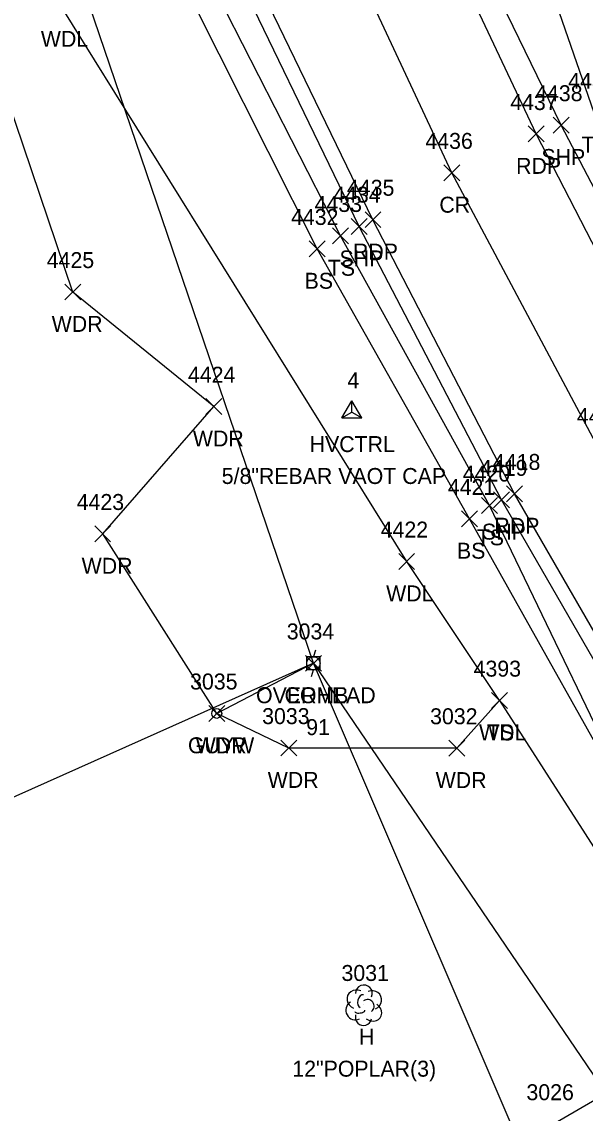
# Model space of a CAD drawing. Extents: x 1601151 to 1602912, y 499508 to 501770.
# Drawn here: x 1601741 to 1601811.7, y 499859.1 to 499996 of the extents above; entities that cross this region are included whole.
import ezdxf

# ---------------------------------------------------------------- set-up
doc = ezdxf.new("R2010")
doc.units = 0
for name, color, linetype in [('C_A', 7, 'Continuous'), ('C_C', 7, 'Continuous'), ('C_I', 7, 'Continuous'), ('CPSM', 7, 'Continuous'), ('L_A', 7, 'Continuous'), ('L_C', 7, 'Continuous'), ('L_I', 7, 'Continuous'), ('L_TIC', 7, 'Continuous'), ('LAWA', 7, 'Continuous'), ('LELB', 7, 'Continuous'), ('LTD', 7, 'Continuous'), ('P_A', 7, 'Continuous'), ('P_I', 7, 'Continuous'), ('P_TIC', 7, 'Continuous'), ('PET', 7, 'Continuous'), ('PRC', 7, 'Continuous'), ('PSP', 7, 'Continuous'), ('R_I', 7, 'Continuous'), ('RDG', 7, 'Continuous'), ('U_A', 7, 'Continuous'), ('U_C', 7, 'Continuous'), ('U_I', 7, 'Continuous'), ('U_TIC', 7, 'Continuous'), ('UCO', 7, 'Continuous'), ('UP', 7, 'Continuous'), ('UPGW', 7, 'Continuous')]:
    doc.layers.add(name, color=color, linetype=linetype)

msp = doc.modelspace()

# ---------------------------------------------------------------- linework, layer by layer
at = {"layer": 'CPSM'}
for p, q in [((1601781.19, 499946.29), (1601782.44, 499948.45)), ((1601783.69, 499946.29), (1601782.44, 499948.45)), ((1601782.44, 499947.01), (1601782.44, 499948.45)), ((1601781.19, 499946.29), (1601782.44, 499947.01)), ((1601781.19, 499946.29), (1601783.69, 499946.29)), ((1601782.44, 499947.01), (1601782.44, 499947.01)), ((1601782.44, 499947.01), (1601783.69, 499946.29))]:
    msp.add_line(p, q, dxfattribs=at)
at = {"layer": 'L_TIC'}
for points in [[(1601780.01, 499968.12), (1601782.01, 499970.12)], [(1601782.01, 499968.12), (1601780.01, 499970.12)], [(1601777.06, 499966.49), (1601779.06, 499968.49)], [(1601779.06, 499966.49), (1601777.06, 499968.49)], [(1601746.4, 499961.08), (1601748.4, 499963.08)], [(1601748.4, 499961.08), (1601746.4, 499963.08)], [(1601764.12, 499946.71), (1601766.12, 499948.71)], [(1601766.12, 499946.71), (1601764.12, 499948.71)], [(1601798.69, 499934.32), (1601800.69, 499936.32)], [(1601800.69, 499934.32), (1601798.69, 499936.32)], [(1601796.18, 499932.64), (1601798.18, 499934.64)], [(1601798.18, 499932.64), (1601796.18, 499934.64)], [(1601750.16, 499930.75), (1601752.16, 499932.75)], [(1601752.16, 499930.75), (1601750.16, 499932.75)], [(1601788.31, 499927.29), (1601790.31, 499929.29)], [(1601790.31, 499927.29), (1601788.31, 499929.29)], [(1601799.97, 499909.85), (1601801.97, 499911.85)], [(1601801.97, 499909.85), (1601799.97, 499911.85)], [(1601799.97, 499909.85), (1601801.97, 499911.85)], [(1601801.97, 499909.85), (1601799.97, 499911.85)], [(1601764.47, 499908.24), (1601766.47, 499910.24)], [(1601766.47, 499908.24), (1601764.47, 499910.24)], [(1601773.51, 499903.9), (1601775.51, 499905.9)], [(1601775.51, 499903.9), (1601773.51, 499905.9)], [(1601794.59, 499903.88), (1601796.59, 499905.88)], [(1601796.59, 499903.88), (1601794.59, 499905.88)]]:
    msp.add_lwpolyline(points, dxfattribs=at)
at = {"layer": 'LAWA'}
for points in [[(1601800.97, 499910.85), (1601789.31, 499928.29), (1601745.98, 499997.83), (1601720.73, 500050.45), (1601707.02, 500079.12), (1601696.06, 500108.93)], [(1601795.59, 499904.88), (1601774.51, 499904.9), (1601765.47, 499909.24), (1601751.16, 499931.75), (1601765.12, 499947.71), (1601747.4, 499962.08), (1601734.99, 499998.67), (1601711.23, 500024.72)], [(1601800.97, 499910.85), (1601795.59, 499904.88)]]:
    msp.add_lwpolyline(points, dxfattribs=at)
at = {"layer": 'LELB'}
for points in [[(1601817.31, 499872.7), (1601822.26, 499874.94), (1601824.19, 499882.19), (1601820.64, 499891.83), (1601797.18, 499933.64), (1601778.06, 499967.49), (1601759.63, 500004.16), (1601735.92, 500054.97), (1601725.84, 500087), (1601715.25, 500119.3), (1601698.06, 500177.62), (1601684.73, 500227.08), (1601672.09, 500269.9), (1601659.22, 500313.1), (1601655.82, 500330.46)], [(1601820.64, 499891.83), (1601799.69, 499935.32), (1601781.01, 499969.12), (1601762.54, 500005.3), (1601740.72, 500057.2), (1601729.05, 500088.56), (1601717.64, 500121.66), (1601699.62, 500177.82), (1601686.02, 500227.23), (1601673.93, 500270.73), (1601661.95, 500313.91), (1601655.82, 500330.46)], [(1601931.2, 499782.14), (1601903.71, 499827.94), (1601870.02, 499876.47), (1601851.57, 499910.98), (1601830.01, 499949.1), (1601812.84, 499984.56), (1601799.79, 500022.21), (1601775.51, 500071.18), (1601768.77, 500104.65), (1601752.69, 500132.35), (1601745.59, 500147.03), (1601736.89, 500188.62), (1601718.63, 500236.24), (1601706.47, 500280.22)], [(1601800.97, 499910.85), (1601817.26, 499885.48), (1601817.31, 499872.7)]]:
    msp.add_lwpolyline(points, dxfattribs=at)
at = {"layer": 'LTD'}
msp.add_line((1601783.9, 499872.69), (1601783.9, 499872.69), dxfattribs=at)
msp.add_line((1601783.9, 499872.69), (1601783.9, 499872.69), dxfattribs=at)
msp.add_arc((1601783.95, 499874.13), 1.05, 335.5272, 180.9563, dxfattribs=at)
for centre, major_axis, ratio, start_param, end_param in [((1601783.11, 499873.36), (1.21, -0.51), 0.895232, 1.570796, 4.712389), ((1601784.94, 499873.28), (-1.14, -0.48), 0.949671, 1.570796, 4.712389), ((1601783.69, 499873.15), (-0.208, -0.792), 0.645439, 3.141593, 6.283185), ((1601784.4, 499872.53), (-0.5, 0.667), 0.989748, 3.141593, 6.283185), ((1601782.82, 499871.99), (0.58, -1.04), 0.959034, 3.141593, 6.283185), ((1601783.44, 499871.94), (-0.625, -0.083), 0.423636, 0, 3.141593), ((1601784.9, 499871.86), (-1.09, 0.79), 0.841452, 1.570796, 4.712389), ((1601783.9, 499871.19), (0.26, 1.06), 0.942809, 1.570796, 4.712389)]:
    msp.add_ellipse(centre, major_axis=major_axis, ratio=ratio, start_param=start_param, end_param=end_param, dxfattribs=at)
at = {"layer": 'P_TIC'}
for points in [[(1601804.55, 499980.9), (1601806.55, 499982.9)], [(1601806.55, 499980.9), (1601804.55, 499982.9)], [(1601807.69, 499982.01), (1601809.69, 499984.01)], [(1601809.69, 499982.01), (1601807.69, 499984.01)], [(1601793.98, 499976.03), (1601795.98, 499978.03)], [(1601795.98, 499976.03), (1601793.98, 499978.03)], [(1601784.08, 499970.15), (1601786.08, 499972.15)], [(1601786.08, 499970.15), (1601784.08, 499972.15)], [(1601782.34, 499969.29), (1601784.34, 499971.29)], [(1601784.34, 499969.29), (1601782.34, 499971.29)], [(1601801.83, 499935.77), (1601803.83, 499937.77)], [(1601803.83, 499935.77), (1601801.83, 499937.77)], [(1601800.22, 499935.03), (1601802.22, 499937.03)], [(1601802.22, 499935.03), (1601800.22, 499937.03)]]:
    msp.add_lwpolyline(points, dxfattribs=at)
at = {"layer": 'PET'}
for points in [[(1601995.67, 499683.24), (1601967.44, 499723.89), (1601951.2, 499747.81), (1601928.38, 499780.82), (1601898.7, 499825.12), (1601866.23, 499874.79), (1601846.19, 499907.84), (1601823.76, 499946.63), (1601805.55, 499981.9), (1601788.87, 500017.29), (1601766.92, 500067.61), (1601755.39, 500098.81), (1601743.92, 500129.72), (1601726.45, 500185.71), (1601711.93, 500234.21), (1601699.42, 500278.31), (1601688.33, 500319.61), (1601682.56, 500342.8), (1601675.53, 500367.54), (1601665.76, 500404.47), (1601656.17, 500441.2), (1601643.95, 500489.36), (1601630.25, 500541.68)], [(1601976.03, 499671.31), (1601949.07, 499710.22), (1601932.5, 499734.59), (1601906.16, 499773.6), (1601879.17, 499813.54), (1601846.78, 499862.77), (1601825.9, 499896.89), (1601802.83, 499936.77), (1601785.08, 499971.15), (1601767.41, 500007.57), (1601745.41, 500058.72), (1601733.84, 500089.25), (1601721.8, 500122.71), (1601703.99, 500178.99), (1601689.71, 500228.27), (1601677.58, 500272.25), (1601666.12, 500315.05), (1601653.43, 500363.86), (1601644.59, 500397.8), (1601635.03, 500435.31), (1601622.92, 500483.99), (1601609.64, 500536.46)]]:
    msp.add_lwpolyline(points, dxfattribs=at)
at = {"layer": 'PRC'}
msp.add_lwpolyline([(1601985.39, 499677.47), (1601958.56, 499716.67), (1601942.32, 499739.6), (1601916.26, 499778.51), (1601888.68, 499819.15), (1601856.54, 499869.05), (1601836.01, 499902.11), (1601813.37, 499942.52), (1601794.98, 499977.03), (1601778.27, 500012.72), (1601755.57, 500062.85), (1601744.49, 500093.78), (1601732.77, 500126.07), (1601715.37, 500182.36), (1601700.57, 500231.28), (1601688.37, 500275.57), (1601676.78, 500317.03), (1601664.23, 500365.85), (1601655.24, 500401.01), (1601645.63, 500438.14), (1601632.99, 500486.74), (1601619.53, 500538.88)], dxfattribs=at)
at = {"layer": 'PSP'}
for points in [[(1601997, 499684.27), (1601969.14, 499725.42), (1601931.2, 499782.14), (1601900.18, 499826.03), (1601867.9, 499875.39), (1601847.37, 499908.8), (1601829.13, 499940.29), (1601829, 499944.33), (1601827.07, 499947.93), (1601808.69, 499983.01), (1601791.36, 500018.61), (1601769.33, 500068.57), (1601758.08, 500099.65), (1601747.15, 500130.33), (1601730.42, 500186.97), (1601714.57, 500235.16), (1601709.05, 500248.69), (1601701, 500279.76), (1601693.52, 500306.69)], [(1601974.74, 499670.12), (1601948.09, 499709.66), (1601931.04, 499733.86), (1601904.81, 499772.45), (1601877.68, 499812.76), (1601851.66, 499852.31), (1601848.35, 499852.94), (1601832.41, 499878.84), (1601831.77, 499883.88), (1601824.29, 499896.03), (1601801.22, 499936.03), (1601783.34, 499970.29), (1601765.73, 500006.71), (1601743.28, 500058.03), (1601731.38, 500088.89), (1601719.94, 500122.25), (1601702, 500178.56), (1601687.75, 500227.8), (1601675.97, 500271.58)]]:
    msp.add_lwpolyline(points, dxfattribs=at)
at = {"layer": 'RDG'}
msp.add_lwpolyline([(1601830.38, 499875.22), (1601826.81, 499868.79), (1601807.74, 499857.74), (1601789.49, 499846.65), (1601768.85, 499838.86), (1601747.32, 499836.92), (1601727.43, 499838.27), (1601705.37, 499845.09), (1601686.43, 499853.19), (1601664.54, 499867.85), (1601655.98, 499874.72), (1601624.93, 499904.1), (1601578.24, 499947.21)], dxfattribs=at)
at = {"layer": 'U_TIC'}
for points in [[(1601776.6, 499914.52), (1601778.6, 499916.52)], [(1601778.6, 499914.52), (1601776.6, 499916.52)], [(1601776.6, 499914.52), (1601778.6, 499916.52)], [(1601778.6, 499914.52), (1601776.6, 499916.52)], [(1601776.6, 499914.52), (1601778.6, 499916.52)], [(1601778.6, 499914.52), (1601776.6, 499916.52)]]:
    msp.add_lwpolyline(points, dxfattribs=at)
at = {"layer": 'UCO'}
for points in [[(1601870.49, 499699.14), (1601777.6, 499915.52), (1601705.51, 500127.03), (1601650.89, 500325.1)], [(1601777.6, 499915.52), (1601720.58, 499890.1)], [(1601777.6, 499915.52), (1601910.46, 499720.23)]]:
    msp.add_lwpolyline(points, dxfattribs=at)
at = {"layer": 'UP'}
for p, q in [((1601777.85, 499917.19), (1601777.6, 499916.36)), ((1601776.76, 499914.69), (1601776.76, 499916.36)), ((1601776.76, 499916.36), (1601778.43, 499916.36)), ((1601778.43, 499916.36), (1601778.43, 499914.69)), ((1601778.43, 499914.69), (1601776.76, 499914.69)), ((1601777.35, 499913.86), (1601777.6, 499914.69)), ((1601777.6, 499915.52), (1601777.6, 499915.52))]:
    msp.add_line(p, q, dxfattribs=at)
msp.add_circle((1601777.6, 499915.52), 0.833, dxfattribs=at)
at = {"layer": 'UPGW'}
msp.add_lwpolyline([(1601777.6, 499915.52), (1601765.47, 499909.24)], dxfattribs=at)
for radius in [0.625, 0.0833]:
    msp.add_circle((1601765.47, 499909.24), radius, dxfattribs=at)

# ---------------------------------------------------------------- texts
at = {"layer": 'C_A'}
msp.add_text('HVCTRL', height=2, dxfattribs=at).set_placement((1601777.13, 499942.01))
at = {"layer": 'C_C'}
msp.add_text('5/8"REBAR VAOT CAP', height=2, dxfattribs=at).set_placement((1601766.1, 499938.01))
at = {"layer": 'C_I'}
msp.add_text('4', height=2, dxfattribs=at).set_placement((1601781.87, 499950.01))
at = {"layer": 'L_A'}
for s, p in [('WDL', (1601743.4, 499992.83)), ('TS', (1601811.25, 499979.56)), ('TS', (1601779.42, 499964.12)), ('BS', (1601776.5, 499962.49)), ('WDR', (1601744.76, 499957.08)), ('WDR', (1601762.48, 499942.71)), ('TS', (1601798.1, 499930.32)), ('BS', (1601795.62, 499928.64)), ('WDR', (1601748.52, 499926.75)), ('WDL', (1601786.73, 499923.29)), ('WDL', (1601798.39, 499905.85)), ('TS', (1601799.38, 499905.85)), ('WDR', (1601762.83, 499904.24)), ('WDR', (1601771.87, 499899.9)), ('WDR', (1601792.95, 499899.88)), ('H', (1601783.33, 499867.69))]:
    msp.add_text(s, height=2, dxfattribs=at).set_placement(p)
at = {"layer": 'L_C'}
msp.add_text('12"POPLAR(3)', height=2, dxfattribs=at).set_placement((1601774.96, 499863.69))
at = {"layer": 'L_I'}
for s, p in [('4439', (1601809.58, 499987.56)), ('4433', (1601777.75, 499972.12)), ('4432', (1601774.8, 499970.49)), ('4425', (1601744.14, 499965.08)), ('4424', (1601761.86, 499950.71)), ('4420', (1601796.35, 499938.32)), ('4421', (1601794.48, 499936.64)), ('4423', (1601747.9, 499934.75)), ('4422', (1601786.05, 499931.29)), ('4393', (1601797.71, 499913.85)), ('4393', (1601797.71, 499913.85)), ('3035', (1601762.13, 499912.24)), ('3033', (1601771.17, 499907.9)), ('3032', (1601792.25, 499907.88)), ('3031', (1601781.13, 499875.69))]:
    msp.add_text(s, height=2, dxfattribs=at).set_placement(p)
at = {"layer": 'P_A'}
for s, p in [('SHP', (1601806.22, 499978.01)), ('RDP', (1601803.04, 499976.9)), ('CR', (1601793.41, 499972.03)), ('RDP', (1601782.57, 499966.15)), ('SHP', (1601780.88, 499965.29)), ('RDP', (1601800.32, 499931.77)), ('SHP', (1601798.76, 499931.03))]:
    msp.add_text(s, height=2, dxfattribs=at).set_placement(p)
at = {"layer": 'P_I'}
for s, p in [('4437', (1601802.3, 499984.9)), ('4438', (1601805.43, 499986.01)), ('4436', (1601791.66, 499980.03)), ('4435', (1601781.82, 499974.15)), ('4434', (1601780.08, 499973.29)), ('4417', (1601810.67, 499945.52)), ('4418', (1601800.14, 499939.77)), ('4419', (1601798.52, 499939.03))]:
    msp.add_text(s, height=2, dxfattribs=at).set_placement(p)
at = {"layer": 'R_I'}
msp.add_text('3026', height=2, dxfattribs=at).set_placement((1601804.34, 499860.74))
at = {"layer": 'U_A'}
for s, p in [('OVERHEAD', (1601770.41, 499910.52)), ('OVERHEAD', (1601770.41, 499910.52)), ('OVERHEAD', (1601770.41, 499910.52)), ('COMB', (1601773.98, 499910.52)), ('GUYW', (1601761.86, 499904.24))]:
    msp.add_text(s, height=2, dxfattribs=at).set_placement(p)
at = {"layer": 'U_C'}
msp.add_text('91', height=2, dxfattribs=at).set_placement((1601776.7, 499906.52))
at = {"layer": 'U_I'}
for s, p in [('3034', (1601774.26, 499918.52)), ('3034', (1601774.26, 499918.52)), ('3034', (1601774.26, 499918.52)), ('3034', (1601774.26, 499918.52)), ('3035', (1601762.13, 499912.24))]:
    msp.add_text(s, height=2, dxfattribs=at).set_placement(p)

doc.saveas('drawing.dxf')
